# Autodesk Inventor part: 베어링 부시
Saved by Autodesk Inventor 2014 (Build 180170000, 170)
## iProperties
Created: 2026-10
Part Number: 베어링 부시
Material: 일반
Document SubType Name: Modeling
Designer: dg
Density: 1 g/cm^3
Appearance: 기본값
Author: dg
Author: jhkim
Creation Date: 2026-09-29
Sending System: Autodesk Inventor 2027
Preprocessor: ST-DEVELOPER v20.1
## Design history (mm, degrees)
node "베어링 부시1"
node "솔리드1"
node "기준1"
